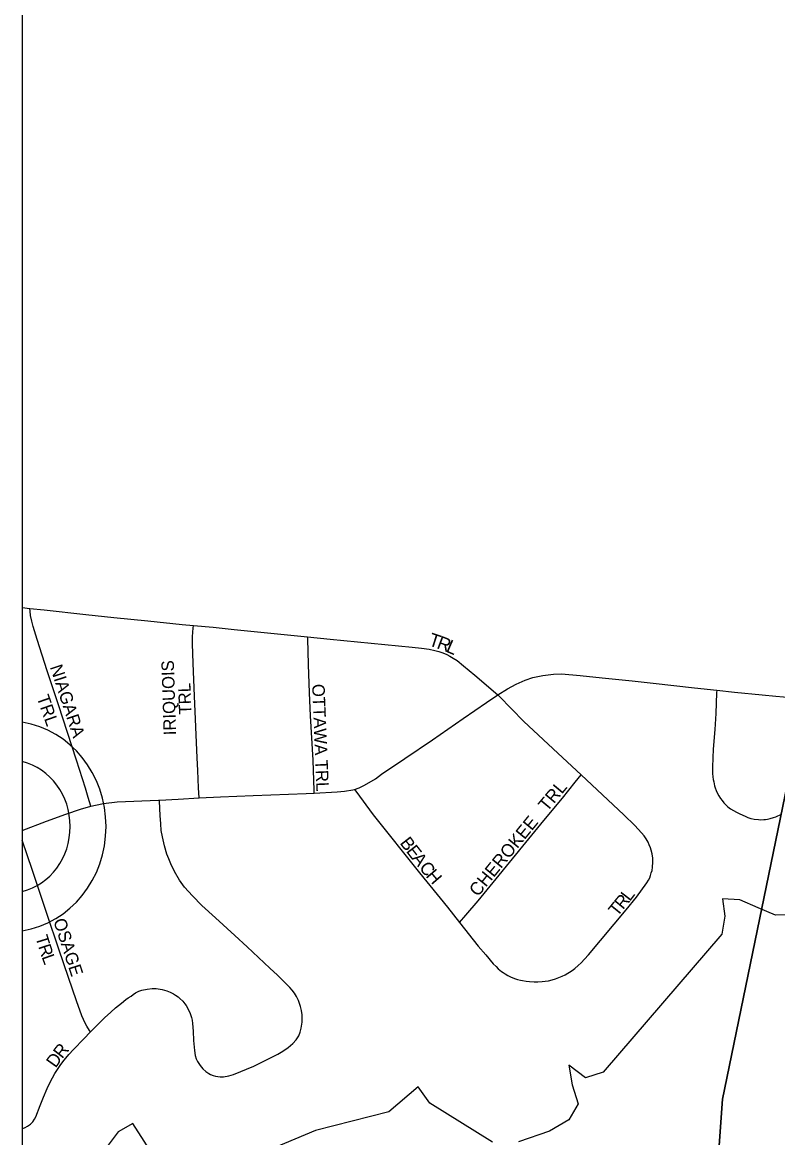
# Model space of a CAD drawing. Extents: x -13.9 to 69.1, y -25.2 to 26.1.
# Drawn here: x 1.757 to 2.268, y 17.221 to 17.974 of the extents above; entities that cross this region are included whole.
import ezdxf

# ---------------------------------------------------------------- set-up
doc = ezdxf.new("R2010")
doc.units = 0
for name, color, linetype in [('GM_X_Major_Lake', 7, 'Continuous'), ('GM_X_Township', 7, 'Continuous'), ('GM_X_Township_Road', 7, 'Continuous'), ('GM_X_Township_Subdivision', 7, 'Continuous'), ('GM_X_Township_Subdivision_Text', 7, 'Continuous'), ('GM_X_Unincorporated', 7, 'Continuous'), ('SH_Data', 7, 'Continuous')]:
    doc.layers.add(name, color=color, linetype=linetype)

msp = doc.modelspace()

# ---------------------------------------------------------------- linework, layer by layer
at = {"layer": 'GM_X_Major_Lake'}
for points in [[(2.29366, 17.37173), (2.26632, 17.37093), (2.25462, 17.37593), (2.24225, 17.3813), (2.23046, 17.38195), (2.23191, 17.37029), (2.22997, 17.35799), (2.14979, 17.26472), (2.13791, 17.26101), (2.12662, 17.26963), (2.1287, 17.25614), (2.13282, 17.24333), (2.12653, 17.23258), (2.11355, 17.2249), (2.09249, 17.21777)], [(2.07495, 17.21746), (2.03266, 17.24388), (2.0248, 17.25497), (2.00489, 17.23801), (1.95539, 17.22537), (1.87577, 17.19203)], [(1.84706, 17.20614), (1.83171, 17.23012), (1.82181, 17.22454), (1.81452, 17.21454)]]:
    msp.add_lwpolyline(points, dxfattribs=at)
at = {"layer": 'GM_X_Township'}
for points in [[(2.20226, 16.14501), (2.21595, 16.45704), (2.17111, 16.462), (2.17937, 16.53249), (2.23038, 17.24665), (2.57136, 18.90232), (2.59954, 20.01177)], [(1.7571, 19.5083), (1.7571, 15.78226)], [(7.86611, 18.45895), (4.52881, 18.78157), (2.57136, 18.90232), (2.23038, 17.24665), (2.17937, 16.53249), (2.17111, 16.462), (2.21595, 16.45704), (2.20226, 16.14501)]]:
    msp.add_lwpolyline(points, dxfattribs=at)
at = {"layer": 'GM_X_Township_Road'}
for points in [[(2.07862, 17.51978), (2.08501, 17.52404), (2.09088, 17.52719), (2.09696, 17.52985), (2.10214, 17.53158), (2.10909, 17.53303), (2.11615, 17.5339), (2.12156, 17.53404), (2.13416, 17.53294), (2.14899, 17.53134), (2.16935, 17.52924), (2.18362, 17.5277), (2.2116, 17.52471), (2.22651, 17.52309)], [(2.22651, 17.52309), (2.23852, 17.52178), (2.25728, 17.51985)], [(1.98164, 17.45599), (1.98487, 17.45704), (1.98848, 17.45875), (1.99577, 17.46319), (1.9999, 17.46618), (2.01565, 17.47683), (2.03443, 17.48955), (2.05517, 17.50377), (2.07098, 17.5147), (2.07862, 17.51978)], [(2.25728, 17.51985), (2.26657, 17.51889), (2.28202, 17.51767), (2.29256, 17.5174), (2.30049, 17.51766)], [(1.95446, 17.45351), (1.96997, 17.45427), (1.97499, 17.45465), (1.98053, 17.45564), (1.98164, 17.45599)], [(1.80344, 17.44452), (1.80661, 17.44539), (1.81199, 17.44644), (1.82127, 17.44751), (1.84926, 17.44871), (1.84987, 17.44874)], [(1.84987, 17.44874), (1.86247, 17.44942), (1.87664, 17.45017)], [(1.87664, 17.45017), (1.89111, 17.45092), (1.91317, 17.45182), (1.94904, 17.45325), (1.95446, 17.45351)], [(1.7571, 17.42808), (1.77349, 17.43448), (1.78653, 17.43927), (1.79652, 17.44262), (1.80344, 17.44452)]]:
    msp.add_lwpolyline(points, dxfattribs=at)
at = {"layer": 'GM_X_Township_Subdivision'}
msp.add_line((1.7571, 17.57885), (1.76225, 17.5783), dxfattribs=at)
for points in [[(1.76225, 17.5783), (1.77197, 17.57726), (1.80012, 17.57424), (1.81905, 17.57221), (1.84198, 17.56988), (1.86513, 17.56753), (1.87291, 17.5668)], [(1.80344, 17.44452), (1.80171, 17.45043), (1.79987, 17.45668), (1.79371, 17.47582), (1.78148, 17.51302), (1.77401, 17.53615), (1.76721, 17.55717), (1.76449, 17.5661), (1.7636, 17.5697), (1.76273, 17.57354), (1.76241, 17.57645), (1.76225, 17.5783)], [(1.87664, 17.45017), (1.87624, 17.45702), (1.8757, 17.46875), (1.87532, 17.47718), (1.8736, 17.51898), (1.87267, 17.54139), (1.87214, 17.55429), (1.87223, 17.5591), (1.87241, 17.5622), (1.87264, 17.56492), (1.87291, 17.5668)], [(1.87291, 17.5668), (1.88605, 17.56556), (1.90031, 17.56399), (1.92728, 17.56128), (1.95, 17.55899)], [(1.95, 17.55899), (1.96525, 17.55746), (1.99296, 17.55486), (2.02066, 17.55209), (2.02704, 17.55146), (2.03209, 17.55069), (2.03604, 17.54983), (2.0386, 17.5492), (2.04145, 17.54825), (2.04401, 17.54707), (2.0462, 17.5459), (2.04847, 17.54463), (2.05096, 17.54298), (2.05524, 17.53952), (2.06302, 17.53323), (2.07862, 17.51978)], [(1.95446, 17.45351), (1.9544, 17.45516), (1.95364, 17.4757), (1.95195, 17.50572), (1.95123, 17.52116), (1.95059, 17.54038), (1.95001, 17.55784), (1.95, 17.55899)], [(2.22651, 17.52309), (2.22643, 17.52112), (2.22591, 17.50729), (2.22514, 17.49645), (2.22421, 17.48312), (2.22392, 17.47729), (2.22362, 17.47108), (2.22367, 17.46872), (2.22378, 17.46672), (2.22393, 17.46443), (2.22422, 17.46255), (2.22449, 17.46095), (2.2251, 17.45838), (2.22555, 17.45695), (2.22616, 17.45523), (2.22707, 17.45326), (2.22806, 17.45153), (2.22903, 17.44989), (2.23011, 17.44838), (2.23141, 17.44682), (2.2327, 17.44547), (2.23406, 17.44418), (2.23581, 17.44287), (2.23777, 17.44166), (2.23999, 17.44047), (2.24213, 17.43932), (2.24565, 17.43778), (2.24751, 17.43697), (2.24957, 17.43636)], [(2.13481, 17.46579), (2.11909, 17.48052), (2.09609, 17.50194), (2.0794, 17.51898), (2.07862, 17.51978)], [(2.05266, 17.36599), (2.06529, 17.35001), (2.07042, 17.34411), (2.07551, 17.3381), (2.07733, 17.33616), (2.0788, 17.33476), (2.08001, 17.33377), (2.08107, 17.33291), (2.08215, 17.33213), (2.08352, 17.33117), (2.08535, 17.33015), (2.08713, 17.32927), (2.08977, 17.32818), (2.09181, 17.32751), (2.09379, 17.327), (2.09522, 17.32673), (2.09762, 17.32636), (2.09997, 17.3261), (2.10305, 17.32588), (2.10567, 17.32586), (2.10848, 17.32599), (2.11058, 17.32626), (2.1128, 17.3266), (2.11522, 17.32716), (2.11758, 17.32787), (2.1199, 17.32874), (2.12213, 17.32968), (2.12414, 17.33066), (2.12585, 17.33166), (2.12703, 17.33236), (2.12875, 17.33361), (2.13061, 17.33498), (2.13295, 17.337), (2.13481, 17.33876), (2.13719, 17.3412), (2.13989, 17.34406), (2.16536, 17.37458), (2.17225, 17.38301), (2.17936, 17.39277), (2.18039, 17.39459), (2.1812, 17.39626), (2.18178, 17.39773), (2.18232, 17.39947), (2.18281, 17.4012), (2.18309, 17.40341), (2.18339, 17.40671), (2.18332, 17.40946), (2.18281, 17.41245), (2.18232, 17.41477), (2.18178, 17.41654), (2.18088, 17.41849), (2.1801, 17.42024), (2.17876, 17.42252), (2.17747, 17.42448), (2.17577, 17.42664), (2.17115, 17.43165), (2.16373, 17.43872), (2.13481, 17.46579)], [(2.05266, 17.36599), (2.05693, 17.37096), (2.06516, 17.38056), (2.07536, 17.39308), (2.09948, 17.42246), (2.10974, 17.43489), (2.12222, 17.44994), (2.13082, 17.46076), (2.13481, 17.46579)], [(1.98164, 17.45599), (1.98251, 17.45482), (1.99426, 17.43877), (2.02557, 17.39954), (2.04453, 17.37627), (2.05266, 17.36599)], [(1.80325, 17.29205), (1.80701, 17.29579), (1.81277, 17.30157), (1.81695, 17.30535), (1.8201, 17.30819), (1.82405, 17.31142), (1.8271, 17.31392), (1.82872, 17.31501), (1.83061, 17.31628), (1.83203, 17.31729), (1.83368, 17.31832), (1.83595, 17.31951), (1.838, 17.32014), (1.84151, 17.321), (1.8448, 17.32131), (1.84765, 17.32131), (1.85175, 17.32061), (1.8549, 17.31975), (1.85716, 17.31888), (1.85932, 17.31778), (1.86074, 17.31691), (1.86248, 17.31577), (1.86365, 17.31471), (1.86559, 17.31277), (1.86696, 17.31108), (1.86783, 17.30983), (1.86914, 17.30739), (1.87063, 17.3044), (1.87149, 17.30176), (1.87193, 17.29992), (1.87213, 17.2978), (1.87251, 17.29251), (1.87285, 17.2861), (1.87354, 17.27953), (1.87405, 17.27607), (1.87464, 17.27387), (1.87544, 17.27198), (1.87632, 17.27056), (1.87734, 17.26923), (1.8791, 17.2671), (1.88121, 17.26528), (1.88312, 17.26396), (1.88436, 17.26325), (1.88604, 17.26262), (1.8878, 17.26215), (1.89094, 17.2616), (1.89306, 17.26167), (1.89672, 17.26223), (1.89994, 17.26333), (1.91369, 17.2688), (1.92407, 17.27395), (1.92979, 17.27705), (1.93328, 17.27906), (1.93672, 17.2815), (1.94001, 17.28418), (1.9422, 17.28677), (1.9441, 17.28945), (1.94498, 17.29189), (1.94571, 17.29464), (1.94623, 17.29858), (1.94637, 17.30149), (1.94619, 17.30354), (1.94574, 17.3065), (1.94513, 17.30928), (1.94375, 17.31321), (1.94248, 17.31589), (1.94104, 17.31825), (1.93957, 17.32029), (1.93786, 17.32203), (1.92968, 17.33032), (1.92451, 17.33508), (1.90916, 17.34942), (1.9007, 17.35718), (1.8878, 17.36912), (1.87852, 17.37754), (1.8721, 17.38394), (1.86942, 17.3869), (1.86683, 17.38992), (1.86347, 17.39449), (1.85988, 17.40047), (1.85749, 17.40567), (1.85604, 17.40896), (1.85488, 17.41213), (1.8532, 17.41769), (1.85187, 17.42395), (1.85099, 17.4282), (1.85065, 17.43261), (1.85024, 17.43837), (1.8499, 17.44791), (1.84987, 17.44874)], [(2.24957, 17.43636), (2.24972, 17.43631), (2.25187, 17.43587), (2.25468, 17.43556), (2.25622, 17.43544), (2.2583, 17.43556), (2.25954, 17.43564), (2.26089, 17.43583), (2.26265, 17.43623), (2.26481, 17.4369), (2.26645, 17.43749), (2.27029, 17.43914)], [(1.80325, 17.29205), (1.80262, 17.29303), (1.80081, 17.29581), (1.79955, 17.29789), (1.79837, 17.30031), (1.79729, 17.30294), (1.79382, 17.31292), (1.78839, 17.32882), (1.78186, 17.34796), (1.77393, 17.37143), (1.76396, 17.40108), (1.7571, 17.42162)], [(1.7571, 17.22669), (1.75756, 17.22682), (1.75909, 17.2274), (1.76072, 17.2282), (1.76269, 17.22964), (1.76413, 17.23123), (1.76523, 17.23304), (1.76614, 17.23464), (1.76926, 17.24231), (1.77152, 17.24798), (1.77394, 17.25369), (1.77577, 17.25758), (1.77755, 17.26097), (1.77905, 17.2638), (1.78139, 17.26739), (1.78322, 17.27009), (1.78543, 17.27292), (1.78863, 17.2767), (1.79178, 17.2802), (1.79858, 17.2874), (1.80325, 17.29205)]]:
    msp.add_lwpolyline(points, dxfattribs=at)
at = {"layer": 'GM_X_Unincorporated'}
for p, q in [((1.7571, 17.50132), (1.7571, 17.36038)), ((1.7571, 17.4748), (1.7571, 17.38689))]:
    msp.add_line(p, q, dxfattribs=at)
for major_axis, start_param, end_param in [((0, 0.07121), 3.286551, 6.138227), ((0, 0.04514), 3.371488, 6.05329)]:
    msp.add_ellipse((1.74754, 17.43085), major_axis=major_axis, ratio=0.929448, start_param=start_param, end_param=end_param, dxfattribs=at)
at = {"layer": 'SH_Data'}
msp.add_line((1.7571, 21.21449), (1.7571, 14.41449), dxfattribs=at)

# ---------------------------------------------------------------- texts
at = {"layer": 'GM_X_Township_Subdivision_Text'}
for s, height, rotation, p in [('T', 0.00901, 342.06689, (2.03113, 17.55338)), ('R', 0.009, 339.35192, (2.03672, 17.55158)), ('L', 0.00898, 336.5545, (2.04292, 17.54925)), ('NIAGARA', 0.008496, 288.01961, (1.77572, 17.53874)), ('IRIQUOIS', 0.008425, 91.77365, (1.86108, 17.49269)), ('TRL', 0.008425, 92.04615, (1.87148, 17.50671)), ('OTTAWA TRL', 0.008426, 272.36784, (1.95299, 17.52706)), ('TRL', 0.008505, 289.21471, (1.76673, 17.51821)), ('TRL', 0.008713, 50.25702, (2.11184, 17.44041)), ('CHEROKEE', 0.008706, 50.8117, (2.06509, 17.38294)), ('B', 0.00869, 307.77759, (2.01193, 17.41963)), ('E', 0.00869, 307.80688, (2.01621, 17.41411)), ('A', 0.00869, 307.78402, (2.02001, 17.40921)), ('C', 0.00871, 309.37222, (2.02493, 17.40287)), ('H', 0.00872, 310.57764, (2.02947, 17.39734)), ('T', 0.00871, 50.81621, (2.15929, 17.36943)), ('R', 0.00871, 50.84429, (2.1632, 17.37423)), ('L', 0.00869, 52.27991, (2.16775, 17.37982)), ('OSAGE', 0.008495, 287.96365, (1.77794, 17.36725)), ('T', 0.00849, 287.28708, (1.76583, 17.35597)), ('R', 0.0085, 288.12538, (1.76776, 17.34977)), ('L', 0.00851, 289.71338, (1.77007, 17.34274)), ('R', 0.00869, 52.12137, (1.78406, 17.27344)), ('D', 0.00866, 54.55154, (1.77961, 17.26719))]:
    msp.add_text(s, height=height, rotation=rotation, dxfattribs=at).set_placement(p)

doc.saveas('drawing.dxf')
